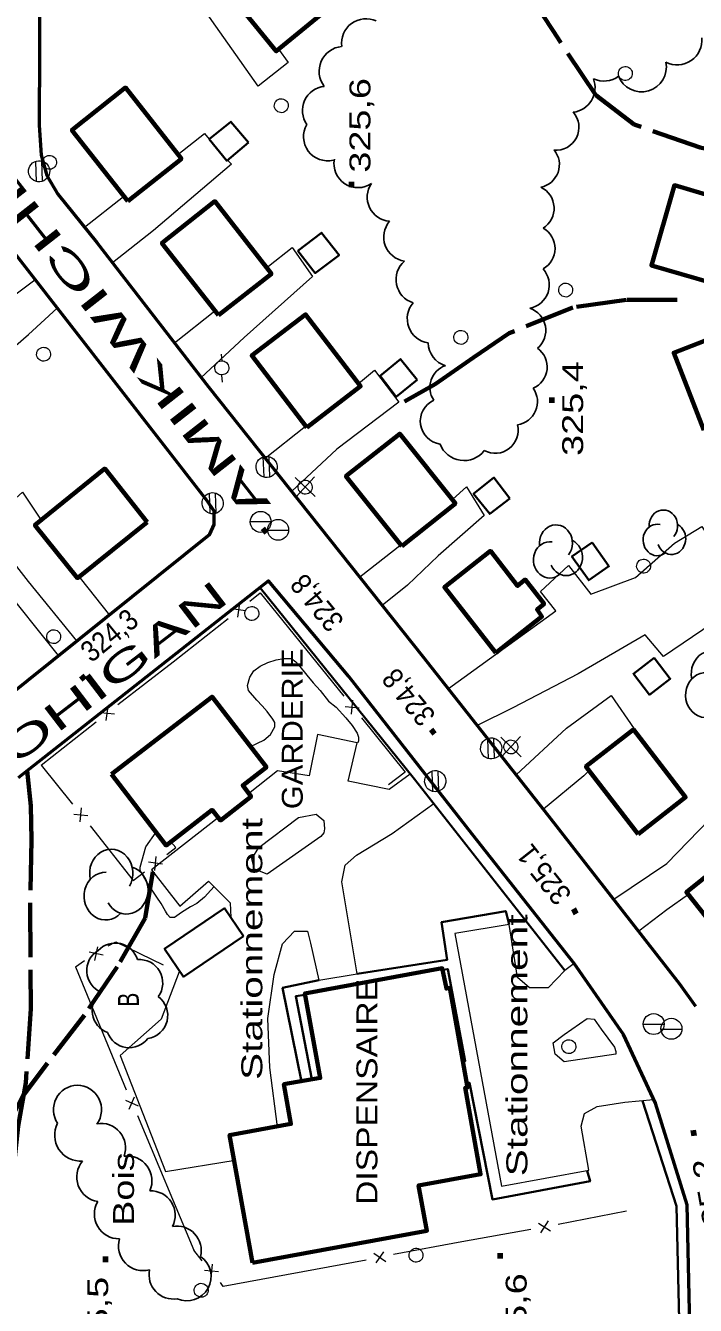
# Model space of a CAD drawing. Extents: x 240591 to 242335, y 5323482 to 5326937.
# Drawn here: x 241043.6 to 241139.6, y 5325072.5 to 5325255.9 of the extents above; entities that cross this region are included whole.
import ezdxf
from ezdxf.enums import TextEntityAlignment as Align

# ---------------------------------------------------------------- set-up
doc = ezdxf.new("R2010")
doc.units = 0
doc.header["$LTSCALE"] = 1.2
doc.linetypes.add('LONG_DASHED', pattern=[7.5, 6, -1.5])
for name, color, linetype, lineweight in [('19', 7, 'Continuous', 13), ('2', 7, 'Continuous', 13), ('21', 7, 'Continuous', 53), ('22', 7, 'LONG_DASHED', 70), ('3', 7, 'Continuous', 140), ('31', 7, 'Continuous', 70), ('36', 7, 'Continuous', 13), ('37', 7, 'Continuous', 13), ('44', 7, 'Continuous', 25), ('52', 7, 'Continuous', 13)]:
    doc.layers.add(name, color=color, linetype=linetype, lineweight=lineweight)

msp = doc.modelspace()

# ---------------------------------------------------------------- linework, layer by layer
at = {"layer": '19'}
for p, q in [((241052, 5325227), (241057.6, 5325231.4)), ((241044.9, 5325219.4), (241027.1, 5325206.2)), ((241064.9, 5325210.4), (241070.7, 5325215)), ((241077.9, 5325193.9), (241083.7, 5325198.5)), ((241091.5, 5325176.9), (241097.4, 5325181.5))]:
    msp.add_line(p, q, dxfattribs=at)
for points in [[(241079.8, 5325252.5), (241081.2, 5325250.6), (241076.9, 5325247.2), (241068.2, 5325259.5), (241063.9, 5325266.4), (241061.7, 5325272.8)], [(241065.4, 5325237.4), (241069.2, 5325240.4), (241069.9, 5325239.6)], [(241072.5, 5325236.6), (241073.1, 5325236), (241061.9, 5325226.5), (241056, 5325221.9)], [(241078.4, 5325221.4), (241081.8, 5325224.1), (241084.7, 5325219.9), (241074.9, 5325211.2), (241068.7, 5325205.4)], [(241048.3, 5325165.6), (241039.7, 5325176.3), (241033.1, 5325186.1), (241028.8, 5325191.6), (241027.6, 5325194.1), (241028.4, 5325197.5), (241030.7, 5325200.6), (241035.5, 5325204.3), (241044, 5325211.6), (241048.1, 5325215.4)], [(241091.3, 5325204.6), (241093.6, 5325206.5), (241097.1, 5325201.9), (241088.2, 5325195.2), (241081.7, 5325189.1)], [(241050.9, 5325167.7), (241044, 5325176.2), (241037.7, 5325184.2), (241043.1, 5325189), (241045.8, 5325185)], [(241104.8, 5325188), (241106.8, 5325189.8), (241109.3, 5325185.7), (241102.7, 5325179.9), (241098.3, 5325175.7), (241094.7, 5325172.8)], [(241104.2, 5325160.9), (241119.6, 5325172), (241117.4, 5325174.8), (241121.4, 5325178.5), (241124.6, 5325174.4), (241131, 5325176.8), (241136.6, 5325181.7), (241140.5, 5325184.1), (241144, 5325178.6), (241144.4, 5325173.4), (241142, 5325170.2), (241135, 5325165.5), (241132.4, 5325168.6), (241122.8, 5325163), (241113.4, 5325158.1), (241108.3, 5325155.6)], [(241051.3, 5325176.9), (241051.4, 5325176.7), (241055.6, 5325171.4)], [(241113.9, 5325148.5), (241121.1, 5325155.2), (241127.5, 5325159.9), (241130.8, 5325155.1), (241130.6, 5325155)], [(241124.3, 5325149.1), (241123.6, 5325148.4), (241117.8, 5325143.6)], [(241127.9, 5325130.7), (241135.5, 5325135.8), (241141.6, 5325142.1), (241144.2, 5325144.8), (241148.2, 5325139.3), (241145.1, 5325136.7)], [(241138.6, 5325131.4), (241135.5, 5325129.2), (241131.5, 5325126.1)]]:
    msp.add_lwpolyline(points, dxfattribs=at)
at = {"layer": '2'}
msp.add_line((241060.8, 5325138.2), (241062.3, 5325140.3), dxfattribs=at)
for points in [[(241075.8, 5325152.6), (241077.7, 5325153.5), (241078.7, 5325154.3), (241079.3, 5325155.4), (241079.3, 5325156), (241079, 5325156.5), (241078.2, 5325157.6), (241077.5, 5325158.4), (241076.7, 5325159.2), (241075.5, 5325160.6), (241075.4, 5325161.3), (241075.7, 5325162.5), (241076.3, 5325163.4), (241077.2, 5325164.1), (241078.3, 5325164.6), (241079.5, 5325165), (241080.6, 5325165.2), (241081.7, 5325165.2), (241082.3, 5325164.7), (241082.7, 5325164.3), (241083.9, 5325162.8), (241084.8, 5325161.7), (241085.8, 5325160.6), (241087, 5325159.1), (241088.1, 5325158.2), (241089.5, 5325156.7), (241090.4, 5325155.6), (241091.1, 5325154.5), (241091.3, 5325153.9), (241091.3, 5325153.4), (241091.2, 5325153.1)], [(241070.6, 5325132.5), (241070.1, 5325132), (241069.2, 5325131), (241068.1, 5325130.1), (241067.2, 5325129.6), (241065.9, 5325128.8), (241064.9, 5325128.1), (241064.3, 5325128.1), (241063.9, 5325128.5), (241063.6, 5325129), (241063, 5325130.1), (241062.4, 5325131), (241060.9, 5325133.2), (241060, 5325134.8), (241060, 5325135.3), (241060.8, 5325138.2)]]:
    msp.add_lwpolyline(points, dxfattribs=at)
at = {"layer": '21'}
for points in [[(241036.3, 5325156), (241070, 5325183), (241070.6, 5325184.4), (241070.6, 5325186.3), (241069.6, 5325187.8), (241036.7, 5325230), (241034.3, 5325231.5), (241030.9, 5325232), (241028.7, 5325231), (241022.5, 5325239.8), (241028.7, 5325245), (241032.3, 5325249.6), (241034.1, 5325253.4), (241034.6, 5325257.8), (241034.7, 5325268.6), (241034.3, 5325310.8), (241034.3, 5325354.7), (241034.2, 5325405), (241034.2, 5325464.4)], [(241045.6, 5325263.3), (241045.5, 5325241.6), (241045.8, 5325237.3), (241046.6, 5325234.4), (241048.2, 5325231.7), (241053.8, 5325224.8), (241069.8, 5325204.1), (241085.7, 5325184.1), (241100.5, 5325165.5), (241118.5, 5325142.7), (241137.3, 5325118.6), (241139.6, 5325115.4)], [(241089.9, 5325162.6), (241078.4, 5325176.3), (241042.5, 5325148.1)], [(240955.4, 5325018.5), (240972, 5325021.4), (240994, 5325025.1), (241022.3, 5325029.9), (241058.6, 5325036.2), (241089.5, 5325041.8), (241114.9, 5325046.3), (241127.6, 5325049), (241130.8, 5325052.2), (241132, 5325054.8), (241139.1, 5325056.5), (241138.4, 5325086.9), (241133.9, 5325101.5), (241129.3, 5325111.3), (241122.2, 5325121.5), (241107.6, 5325140), (241089.9, 5325162.6)]]:
    msp.add_lwpolyline(points, dxfattribs=at)
at = {"layer": '22'}
for points in [[(241158.6, 5325234.6), (241149.7, 5325236.5), (241140.3, 5325238.4), (241130.8, 5325241.7), (241125.3, 5325245.9), (241119.9, 5325254), (241115.2, 5325261.3), (241110.8, 5325267.3), (241110.3, 5325270.3)], [(241137, 5325216.6), (241129.7, 5325216.6), (241122, 5325215.5), (241112.9, 5325211.8), (241107.8, 5325208.3), (241102.3, 5325204.5), (241097.9, 5325202)], [(241043.8, 5325149.1), (241044.3, 5325144.1), (241044.4, 5325139.2), (241044.2, 5325129.6), (241044.3, 5325115), (241043.6, 5325104.4), (241042.5, 5325098.2), (241041.5, 5325088.6), (241040.5, 5325079), (241040.5, 5325068.6), (241040.5, 5325063.2), (241040.5, 5325057.1), (241040.4, 5325053.1)], [(241061.8, 5325134.6), (241060.7, 5325128), (241056.7, 5325121), (241052, 5325114.1), (241046.7, 5325107.2), (241043.2, 5325102.6), (241039.6, 5325095.7), (241035.2, 5325087.7), (241031.4, 5325080.4), (241029.8, 5325075.4), (241028.3, 5325066.4), (241027.2, 5325062.6), (241025, 5325060)]]:
    msp.add_lwpolyline(points, dxfattribs=at)
at = {"layer": '22', "linetype": 'Continuous', "lineweight": 35}
for points in [[(241077.2, 5325175.3), (241099.3, 5325147.9), (241120.9, 5325120.5)], [(241112.9, 5325127.1), (241112.4, 5325129), (241103.2, 5325127.4), (241104, 5325122), (241091.1, 5325120)], [(241085.6, 5325119.1), (241080.4, 5325118), (241083.1, 5325104.6)], [(241103.4, 5325120.6), (241104.1, 5325120.7), (241106.6, 5325107.5), (241106.2, 5325107.5)], [(241084.6, 5325104.9), (241082.3, 5325116.8), (241083.6, 5325117)], [(241106.8, 5325104.4), (241107.2, 5325104.4), (241110.5, 5325087.7), (241124.5, 5325090.3), (241124.1, 5325091.8)], [(241132, 5325101.8), (241136.9, 5325086.7), (241137.6, 5325056.2)]]:
    msp.add_lwpolyline(points, dxfattribs=at)
at = {"layer": '3'}
for p, q in [((241090.3, 5325232.7), (241090.3, 5325233.5)), ((241119, 5325201.8), (241119, 5325202.6)), ((241077.6, 5325183.8), (241078.1, 5325183.2)), ((241051.5, 5325162.2), (241052.1, 5325162.7)), ((241101.7, 5325155), (241102.2, 5325154.4)), ((241122.1, 5325129.3), (241122.5, 5325128.6)), ((241139.3, 5325097.6), (241139.4, 5325096.8)), ((241055, 5325078.7), (241055, 5325079.5)), ((241111.6, 5325079.2), (241111.6, 5325080))]:
    msp.add_line(p, q, dxfattribs=at)
at = {"layer": '31'}
for points in [[(241074.2, 5325258.7), (241084.2, 5325266.9), (241089.5, 5325260.4), (241079.5, 5325252.2)], [(241058.2, 5325230.7), (241050.2, 5325240.9), (241057.9, 5325247), (241065.9, 5325236.8)], [(241145.1, 5325230.5), (241141.9, 5325219), (241133.3, 5325221.5), (241136.6, 5325233)], [(241071.2, 5325214.4), (241063.1, 5325224.7), (241070.7, 5325230.7), (241078.8, 5325220.3)], [(241083.9, 5325198.3), (241076, 5325208.6), (241083.7, 5325214.5), (241091.6, 5325204.2)], [(241140.8, 5325197.9), (241136.5, 5325209), (241144.5, 5325212.1), (241148.7, 5325201)], [(241097.5, 5325181.3), (241089.5, 5325191.3), (241097.2, 5325197.4), (241105.2, 5325187.4)], [(241061, 5325184.7), (241051, 5325176.7), (241044.9, 5325184.3), (241054.9, 5325192.4)], [(241111, 5325166), (241103.6, 5325175.4), (241110.2, 5325180.6), (241114.1, 5325175.6), (241115.2, 5325176.5), (241117.9, 5325173), (241116.9, 5325172.2), (241117.6, 5325171.2)], [(241055.9, 5325148.6), (241070.3, 5325159.7), (241078.1, 5325149.6), (241074.7, 5325147), (241075.9, 5325145.4), (241071.5, 5325142), (241070.3, 5325143.5), (241063.7, 5325138.4)], [(241131.4, 5325140), (241123.9, 5325149.7), (241130.7, 5325155), (241138.2, 5325145.3)], [(241144.9, 5325137), (241152.4, 5325127.6), (241145.8, 5325122.3), (241138.3, 5325131.7)], [(241076.1, 5325078.6), (241072.8, 5325096.9), (241081.6, 5325098.5), (241080.6, 5325104.2), (241085.8, 5325105.1), (241083.6, 5325117.2), (241103.3, 5325120.8), (241103.9, 5325117.9), (241104.4, 5325118), (241106.9, 5325103.7), (241106.6, 5325103.7), (241108.8, 5325091.3), (241099.9, 5325089.7), (241101.1, 5325083.2)]]:
    msp.add_lwpolyline(points, close=True, dxfattribs=at)
at = {"layer": '31', "lineweight": 35}
for points in [[(241075.5, 5325239.1), (241072.4, 5325236.5), (241069.9, 5325239.6), (241073, 5325242.1)], [(241082.6, 5325223.6), (241086, 5325226.2), (241088.5, 5325223), (241085.1, 5325220.4)], [(241099.7, 5325205.1), (241096.7, 5325202.7), (241094.4, 5325205.7), (241097.3, 5325208.1)], [(241113, 5325188.1), (241110.1, 5325185.9), (241107.8, 5325188.8), (241110.7, 5325191.1)], [(241124.8, 5325181.8), (241127.2, 5325178.4), (241124.3, 5325176.4), (241121.9, 5325179.8)], [(241133.7, 5325165.3), (241136, 5325162.3), (241133, 5325160), (241130.7, 5325163)], [(241074.8, 5325125.4), (241066.2, 5325119.6), (241063.5, 5325123.6), (241072.1, 5325129.4)]]:
    msp.add_lwpolyline(points, close=True, dxfattribs=at)
at = {"layer": '36'}
for p, q in [((241045, 5325236.4), (241045.1, 5325233.5)), ((241046, 5325233.6), (241045.9, 5325236.5)), ((241071.6, 5325208.8), (241071.7, 5325207.8)), ((241071.8, 5325204.8), (241071.7, 5325205.8)), ((241077.6, 5325194.1), (241077.7, 5325191.2)), ((241078.6, 5325191.2), (241078.5, 5325194.1)), ((241085.1, 5325188.4), (241082.2, 5325191.1)), ((241082.3, 5325188.3), (241085, 5325191.2)), ((241069.9, 5325188.9), (241070, 5325186)), ((241070.9, 5325186), (241070.8, 5325188.9)), ((241075.8, 5325184.8), (241078.8, 5325184.8)), ((241078.3, 5325183.6), (241081.3, 5325183.6)), ((241114.6, 5325151.1), (241111.7, 5325153.9)), ((241111.8, 5325151.1), (241114.5, 5325154)), ((241109.8, 5325153.7), (241109.9, 5325150.8)), ((241110.8, 5325150.9), (241110.7, 5325153.8)), ((241101.8, 5325149), (241101.9, 5325146.1)), ((241102.8, 5325146.2), (241102.7, 5325149.1)), ((241132.1, 5325112.8), (241135.1, 5325112.8)), ((241134.7, 5325112.1), (241137.7, 5325112.1))]:
    msp.add_line(p, q, dxfattribs=at)
for centre in [(241077.269, 5325184.762), (241079.769, 5325183.622), (241133.619, 5325112.812), (241136.159, 5325112.142)]:
    msp.add_circle(centre, 1.5, dxfattribs=at)
for centre, major_axis in [((241129.553, 5325249.01), (0.261, -0.965)), ((241080.223, 5325244.39), (0.261, -0.965)), ((241045.504, 5325234.997), (-0.396, 1.465)), ((241046.993, 5325236.28), (0.261, -0.965)), ((241120.993, 5325217.98), (0.261, -0.965)), ((241105.973, 5325211.2), (0.261, -0.965)), ((241046.143, 5325208.78), (0.261, -0.965)), ((241071.691, 5325206.829), (-0.261, 0.965)), ((241078.114, 5325192.637), (-0.396, 1.465)), ((241083.654, 5325189.727), (-0.261, 0.965)), ((241070.384, 5325187.437), (-0.396, 1.465)), ((241132.173, 5325178.42), (0.261, -0.965)), ((241076.003, 5325171.64), (0.261, -0.965)), ((241047.583, 5325168.32), (0.261, -0.965)), ((241110.314, 5325152.307), (-0.396, 1.465)), ((241113.144, 5325152.517), (-0.261, 0.965)), ((241102.294, 5325147.617), (-0.396, 1.465)), ((241121.453, 5325109.57), (0.261, -0.965)), ((241099.533, 5325079.69), (0.261, -0.965)), ((241068.733, 5325074.67), (0.261, -0.965))]:
    msp.add_ellipse(centre, major_axis=major_axis, ratio=0.99964, dxfattribs=at)
at = {"layer": '37'}
for p, q in [((241075.1, 5325172), (241073.1, 5325172.3)), ((241074, 5325171.1), (241074.3, 5325173.1)), ((241064.7, 5325164.7), (241072.6, 5325170.9)), ((241082.9, 5325167.6), (241089.2, 5325159.8)), ((241056.8, 5325158.6), (241064.7, 5325164.7)), ((241055.1, 5325156.3), (241055.4, 5325158.3)), ((241089.4, 5325158.3), (241091.4, 5325158.1)), ((241090.3, 5325157.2), (241090.5, 5325159.2)), ((241045.8, 5325149.9), (241053.7, 5325156.1)), ((241056.3, 5325157.2), (241054.3, 5325157.4)), ((241045.8, 5325149.9), (241050.3, 5325144.3)), ((241050.5, 5325142.9), (241052.5, 5325142.7)), ((241051.4, 5325141.8), (241051.6, 5325143.8)), ((241052.8, 5325141.2), (241059, 5325133.4)), ((241063.2, 5325135.7), (241061.2, 5325136)), ((241062.1, 5325134.8), (241062.3, 5325136.8)), ((241059, 5325133.4), (241060.6, 5325134.6)), ((241054.7, 5325122.7), (241052.7, 5325123.1)), ((241053.5, 5325121.9), (241053.9, 5325123.9)), ((241050.7, 5325121), (241052, 5325121.9)), ((241050.7, 5325121), (241058, 5325103.4)), ((241057.9, 5325101.9), (241059.7, 5325101.1)), ((241058.4, 5325100.6), (241059.2, 5325102.4)), ((241059.6, 5325099.7), (241067.7, 5325080.4)), ((241117.1, 5325084.3), (241118.8, 5325083.2)), ((241118.5, 5325084.6), (241117.4, 5325082.9)), ((241129.7, 5325086), (241119.9, 5325084.1)), ((241116, 5325083.4), (241106.1, 5325081.6)), ((241106.1, 5325081.6), (241096.3, 5325079.8)), ((241068.9, 5325078.9), (241067.7, 5325080.4)), ((241092.4, 5325079), (241071.9, 5325075.2)), ((241093.5, 5325080), (241095.2, 5325078.8)), ((241094.9, 5325080.2), (241093.8, 5325078.6)), ((241071.2, 5325077.3), (241069.2, 5325077.5)), ((241070.3, 5325078.4), (241070.1, 5325076.4)), ((241071.9, 5325075.2), (241071.5, 5325075.8))]:
    msp.add_line(p, q, dxfattribs=at)
for points in [[(241075.7, 5325173.4), (241077.2, 5325174.6), (241082.9, 5325167.6)], [(241091.7, 5325156.7), (241098, 5325148.9), (241095.6, 5325147.1)], [(241063.8, 5325137.1), (241065.1, 5325138.1), (241064.4, 5325138.9)], [(241055.4, 5325124), (241056.5, 5325124.6), (241063.3, 5325121.3)]]:
    msp.add_lwpolyline(points, dxfattribs=at)
at = {"layer": '44'}
for centre, radius, start, end in [((241089.22, 5325249.325), 3.571, 95.46785, 217.31544), ((241086.873, 5325239.953), 3.459, 149.60433, 283.49576), ((241096.005, 5325231.291), 3.462, 145.37139, 265.6041), ((241098.401, 5325225.58), 3.491, 139.65585, 261.25817), ((241100.15, 5325219.493), 3.486, 130.84878, 252.98657), ((241055.655, 5325120.482), 3.335, 120.51549, 248.05864), ((241056.408, 5325121.089), 3.335, 16.68037, 137.17847), ((241059.891, 5325118.725), 3.333, 323.62346, 95.00108), ((241056.433, 5325114.748), 3.327, 127.46509, 250.33678), ((241060.61, 5325114.053), 3.335, 278.24134, 53.90812), ((241058.435, 5325112.752), 3.322, 200.00439, 323.02181), ((241051.443, 5325096.89), 3.711, 152.55892, 274.42928), ((241054.441, 5325090.9), 3.549, 139.81734, 261.55435), ((241056.957, 5325085.583), 3.534, 149.24358, 271.02884), ((241060.418, 5325081.029), 3.548, 163.27948, 284.8893)]:
    msp.add_arc(centre, radius, start, end, dxfattribs=at)
for centre, major_axis, ratio, start_param, end_param in [((241092.385, 5325253.325), (-1.392, -3.247), 0.999995, 3.1188882, 5.2435801), ((241136.975, 5325253.814), (1.525, 3.228), 0.999995, 3.1135911, 5.2453738), ((241131.883, 5325249.926), (3.106, -1.714), 0.999467, 4.0052413, 6.9875004), ((241121.652, 5325247), (0.876, 3.451), 0.999809, 3.5114128, 5.3209433), ((241126.463, 5325251.476), (0.258, -3.546), 0.994417, 5.7778475, 6.8507007), ((241086.706, 5325243.717), (-1.339, -3.188), 0.999985, 3.6336527, 5.7337953), ((241119.587, 5325241.311), (0.135, 3.311), 0.999673, 3.094817, 5.4725871), ((241091.221, 5325236.096), (-2.38, -2.494), 0.99793, 5.2853106, 7.6442707), ((241116.799, 5325235.956), (0.958, 3.157), 0.999737, 3.6319294, 5.6948992), ((241115.948, 5325229.69), (3.381, 0.215), 0.995821, 5.2135518, 7.3346346), ((241116.142, 5325223.933), (3.312, -0.331), 0.99957, 5.3161961, 7.4456521), ((241115.24, 5325218.719), (-0.71, 3.331), 0.999995, 3.1148528, 5.2445346), ((241101.795, 5325213.879), (2.727, -2.206), 0.999995, 3.1137782, 5.2450412), ((241114.802, 5325212.196), (3.288, 0.624), 0.999713, 5.2216462, 7.3446946), ((241104.736, 5325210.458), (3.066, -1.596), 0.999985, 3.6354355, 4.9072059), ((241115.035, 5325206.944), (3.286, -0.352), 0.997826, 5.2217447, 7.3421626), ((241104.832, 5325204.031), (0.209, -3.299), 0.99988, 3.4091969, 5.2340586), ((241113.655, 5325201.964), (1.436, 2.98), 0.999736, 3.7209823, 5.7901819), ((241103.46, 5325199.192), (1.135, -3.105), 0.999736, 3.2185257, 5.7899148), ((241110.887, 5325197.888), (3.254, -0.542), 0.999886, 4.3857861, 6.6924168), ((241106.422, 5325197.22), (2.266, 2.888), 0.999985, 2.5982344, 4.7212811), ((241135.002, 5325184.205), (-0.002, 2.256), 0.905549, 3.9589338, 7.9288088), ((241119.606, 5325181.727), (-0.002, 2.607), 0.905549, 4.017709, 7.9875841), ((241134.137, 5325182.174), (-0.002, 2.256), 0.905549, 6.0855511, 10.0245601), ((241136.163, 5325182.348), (-0.002, 2.256), 0.905549, 1.9460053, 5.8325806), ((241118.732, 5325179.32), (-0.002, 2.607), 0.905549, 6.1443263, 10.0833353), ((241121.059, 5325179.672), (-0.002, 2.607), 0.905549, 2.0047805, 5.8913558), ((241141.921, 5325163.025), (-0.003, 3.227), 0.905548, 4.1152807, 8.0851557), ((241141.108, 5325159.943), (-0.003, 3.227), 0.905548, 6.241898, 10.180907), ((241055.845, 5325134.43), (-0.003, 3.421), 0.905548, 4.1329346, 8.1028096), ((241055.035, 5325131.146), (-0.003, 3.421), 0.905548, 6.2595519, 10.1985609), ((241058.02, 5325131.993), (-0.003, 3.421), 0.905548, 2.1200061, 6.0065814), ((241051.074, 5325100.543), (-1.649, -3.1), 0.999631, 3.6632195, 5.7875261), ((241050.94, 5325100.541), (-0.46, 3.481), 0.999041, 3.9566437, 6.14584), ((241054.396, 5325095.081), (-0.402, 3.48), 0.998844, 4.2445674, 6.3453442), ((241058.146, 5325090.364), (2.831, 2.121), 0.999953, 5.2165683, 7.3431384), ((241061.519, 5325085.416), (-0.685, 3.43), 0.999222, 4.0361813, 6.1284179), ((241065.241, 5325080.369), (-3.172, 1.491), 0.999125, 3.335819, 5.3348008), ((241066.671, 5325076.644), (-2.51, 2.434), 0.999094, 1.9317854, 4.8814087), ((241064.76, 5325076.905), (2.692, -2.237), 0.999276, 3.6354952, 5.5569236)]:
    msp.add_ellipse(centre, major_axis=major_axis, ratio=ratio, start_param=start_param, end_param=end_param, dxfattribs=at)
at = {"layer": '52'}
for points in [[(241098.7, 5325148.6), (241095.7, 5325146.4), (241089.8, 5325147.6), (241091.1, 5325153.1), (241085.4, 5325154.3), (241084.2, 5325148.4), (241079.7, 5325149.1), (241075.5, 5325145.8)], [(241079.7, 5325098.1), (241078.6, 5325106.6), (241078.3, 5325113.6), (241079.2, 5325119.9), (241080.4, 5325124.3), (241082.1, 5325126.1), (241084, 5325126.1), (241084.4, 5325124.4), (241085.6, 5325119.1), (241091.1, 5325120), (241088.9, 5325133.2), (241089.4, 5325135.6), (241091, 5325137), (241096.1, 5325140.1), (241102.1, 5325144.4)], [(241071.2, 5325142.4), (241061.6, 5325134.9), (241065.7, 5325129.7), (241069.8, 5325133.3), (241072.9, 5325130.2), (241073, 5325128.1)], [(241122.2, 5325121.5), (241120.9, 5325120.5), (241118.5, 5325118), (241115.8, 5325118), (241114.1, 5325119.5), (241112.9, 5325127.1), (241105.1, 5325125.8), (241111.8, 5325089.6), (241124.3, 5325091.9), (241123.2, 5325098.2), (241123.7, 5325100), (241125.5, 5325101), (241129.5, 5325101.6), (241133.6, 5325102)], [(241065.7, 5325120.4), (241065.6, 5325120.3), (241063, 5325113.5), (241057.1, 5325108.3), (241063.6, 5325091.7), (241073.6, 5325093.3)]]:
    msp.add_lwpolyline(points, dxfattribs=at)
for points in [[(241085.9, 5325139.7), (241078.2, 5325134.3), (241076.4, 5325135), (241076, 5325136.5), (241077, 5325138.1), (241082.7, 5325142.4), (241085.2, 5325142.9), (241086.3, 5325142), (241086.4, 5325140.8), (241086.3, 5325140.2)], [(241128.2, 5325108.5), (241120.8, 5325107.4), (241119.5, 5325108.5), (241119.2, 5325110.1), (241120.8, 5325111.3), (241124.1, 5325113.6), (241125.1, 5325113.5), (241126.1, 5325112.1), (241128, 5325109.5), (241128.2, 5325108.9)]]:
    msp.add_lwpolyline(points, close=True, dxfattribs=at)

# ---------------------------------------------------------------- texts
at = {"layer": '21'}
for s, rotation, width, p in [('AMIKWICHE', 128.009, 2.05, (241078.8, 5325187.3)), ('MOHIGAN', 37.437, 1.85, (241035.4, 5325144.7))]:
    msp.add_text(s, height=4, rotation=rotation, dxfattribs=dict(at, width=width)).set_placement(p)
at = {"layer": '3'}
for s, height, rotation, width, p in [('325,6', 3, 90, 1.35, (241093, 5325234.8)), ('324,3', 3, 39.169, 0.9, (241053, 5325164.5)), ('324,8', 2.999, 129.521, 0.9, (241102.5, 5325157.1)), ('325,1', 2.999, 128.283, 0.95, (241122, 5325131.4))]:
    msp.add_text(s, height=height, rotation=rotation, dxfattribs=dict(at, width=width)).set_placement(p)
at = {"layer": '3', "width": 1.35}
msp.add_text('325,4', height=3, rotation=90, dxfattribs=at).set_placement((241123.5, 5325201), align=Align.CENTER)
at = {"layer": '3'}
for s, rotation, width, p in [('324,8', 129.638, 0.9, (241083.595, 5325177.586)), ('325,2', 100.046, 1.25, (241142.036, 5325093.777)), ('325,5', 90, 1.35, (241055.4, 5325076.6)), ('325,6', 90, 1.35, (241115.4, 5325077.1))]:
    msp.add_text(s, height=3, rotation=rotation, dxfattribs=dict(at, width=width)).set_placement(p, align=Align.RIGHT)
at = {"layer": '31'}
for s, width, p in [('GARDERIE', 1.1, (241083.3, 5325143.6)), ('DISPENSAIRE', 1.2, (241094, 5325086.9))]:
    msp.add_text(s, height=3, rotation=90, dxfattribs=dict(at, width=width)).set_placement(p)
at = {"layer": '44'}
for s, width, p in [('B', 0.75, (241059.8, 5325115.3)), ('Bois', 1.35, (241059.1, 5325083.9))]:
    msp.add_text(s, height=3, rotation=90, dxfattribs=dict(at, width=width)).set_placement(p)
at = {"layer": '52', "width": 1.45}
for p in [(241077.5, 5325104.8), (241115.5, 5325091)]:
    msp.add_text('Stationnement', height=3, rotation=90, dxfattribs=at).set_placement(p)

doc.saveas('drawing.dxf')
